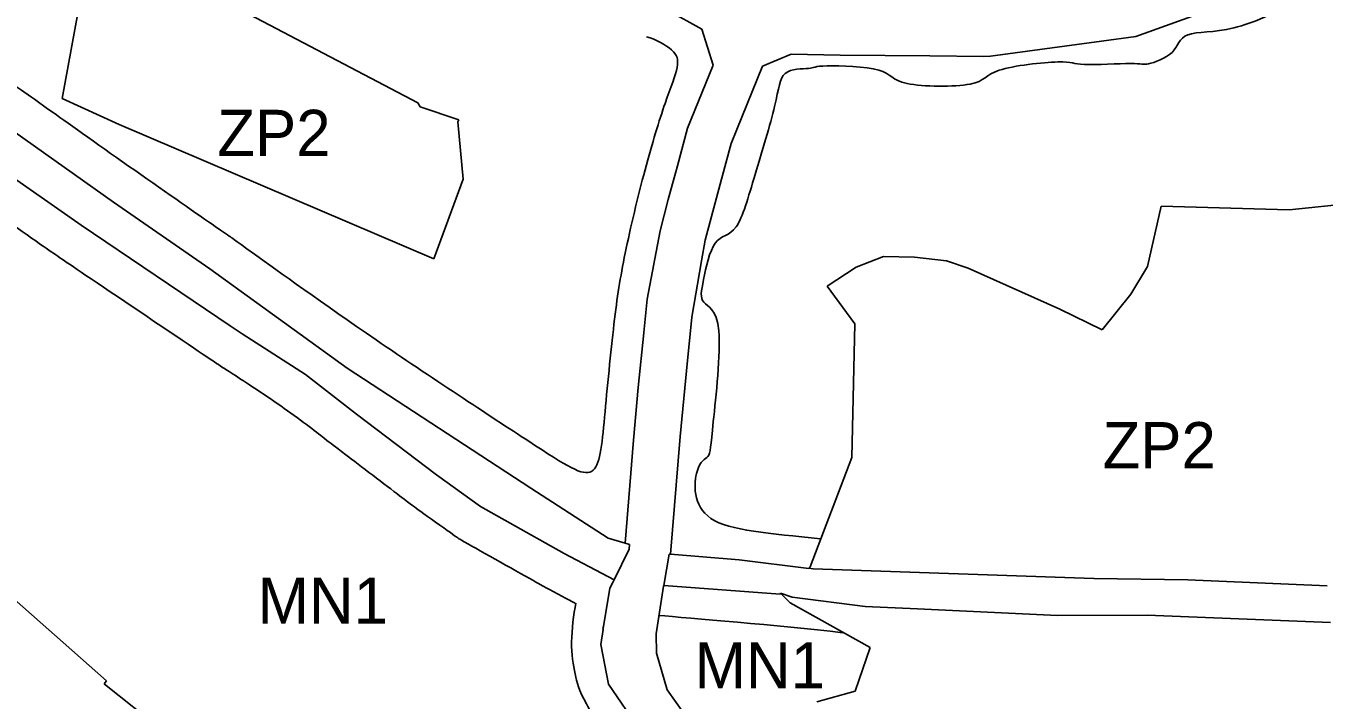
# Model space of a CAD drawing. Extents: x 7413438 to 7416393, y 5541665 to 5544118.
# Drawn here: x 7414274.3 to 7414442.9, y 5542859.3 to 5542946.8 of the extents above; entities that cross this region are included whole.
import ezdxf

# ---------------------------------------------------------------- set-up
doc = ezdxf.new("R2010")
doc.units = 0
for name, color, linetype in [('linie_rozgraniczajace', 7, 'Continuous'), ('linie_zabudowy_nieprzekraczalne', 7, 'Continuous'), ('oznaczenia_przeznaczen', 7, 'Continuous')]:
    doc.layers.add(name, color=color, linetype=linetype)

msp = doc.modelspace()

# ---------------------------------------------------------------- linework, layer by layer
at = {"layer": 'linie_rozgraniczajace'}
for p, q in [((7414283.71, 5542963.14), (7414278.97, 5542937.43)), ((7414325.17, 5542936.87), (7414296.63, 5542951.85)), ((7414357.68, 5542948.84), (7414362.05, 5542946.44)), ((7414418.45, 5542945.45), (7414428.42, 5542949.06)), ((7414362.05, 5542946.44), (7414363.54, 5542941.74)), ((7414413.98, 5542944.85), (7414418.45, 5542945.45)), ((7414399.57, 5542942.9), (7414413.98, 5542944.85)), ((7414369.96, 5542941.6), (7414373.68, 5542943.17)), ((7414373.68, 5542943.17), (7414380.04, 5542943.04)), ((7414380.04, 5542943.04), (7414391.66, 5542942.94)), ((7414391.66, 5542942.94), (7414398.64, 5542942.88)), ((7414398.64, 5542942.88), (7414399.57, 5542942.9)), ((7414363.54, 5542941.74), (7414360.21, 5542933.57)), ((7414366.62, 5542933.4), (7414369.96, 5542941.6)), ((7414278.97, 5542937.43), (7414286.37, 5542934.05)), ((7414325.47, 5542936.32), (7414325.17, 5542936.87)), ((7414330.48, 5542934.63), (7414325.47, 5542936.32)), ((7414286.37, 5542934.05), (7414327.24, 5542916.61)), ((7414330.39, 5542934.37), (7414330.48, 5542934.63)), ((7414331.06, 5542926.96), (7414330.39, 5542934.37)), ((7414360.21, 5542933.57), (7414358.89, 5542928.66)), ((7414272.83, 5542933.05), (7414285.64, 5542923.95)), ((7414365.88, 5542931.58), (7414366.62, 5542933.4)), ((7414281.45, 5542920.96), (7414266.51, 5542931.38)), ((7414364.63, 5542926.93), (7414365.88, 5542931.58)), ((7414358.89, 5542928.66), (7414357.71, 5542924.3)), ((7414327.24, 5542916.61), (7414331.06, 5542926.96)), ((7414362.51, 5542919.03), (7414364.63, 5542926.93)), ((7414285.64, 5542923.95), (7414298.14, 5542915.29)), ((7414357.71, 5542924.3), (7414356.63, 5542920.23)), ((7414419.97, 5542915.61), (7414421.72, 5542923.44)), ((7414421.72, 5542923.44), (7414438.34, 5542922.97)), ((7414438.34, 5542922.97), (7414446.71, 5542923.83)), ((7414300.81, 5542907.9), (7414281.45, 5542920.96)), ((7414356.63, 5542920.23), (7414354.98, 5542911.35)), ((7414362, 5542916.32), (7414362.51, 5542919.03)), ((7414382.1, 5542915.51), (7414385.67, 5542916.89)), ((7414385.67, 5542916.89), (7414389.7, 5542916.8)), ((7414389.7, 5542916.8), (7414393.86, 5542916.36)), ((7414298.14, 5542915.29), (7414316, 5542902.41)), ((7414360.77, 5542909.03), (7414362, 5542916.32)), ((7414378.35, 5542913.03), (7414382.1, 5542915.51)), ((7414393.86, 5542916.36), (7414396.67, 5542915.39)), ((7414396.67, 5542915.39), (7414408.56, 5542910.06)), ((7414417.78, 5542912), (7414419.97, 5542915.61)), ((7414380.86, 5542909.63), (7414378.35, 5542913.03)), ((7414414.06, 5542907.4), (7414417.78, 5542912)), ((7414354.98, 5542911.35), (7414354.54, 5542907.03)), ((7414408.56, 5542910.06), (7414414.06, 5542907.4)), ((7414360.05, 5542902.04), (7414360.77, 5542909.03)), ((7414381.94, 5542908.16), (7414380.86, 5542909.63)), ((7414302.34, 5542906.88), (7414300.81, 5542907.9)), ((7414310.6, 5542901.57), (7414302.34, 5542906.88)), ((7414354.54, 5542907.01), (7414353.8, 5542899.89)), ((7414354.54, 5542907.03), (7414354.54, 5542907.01)), ((7414381.54, 5542890.81), (7414381.94, 5542908.16)), ((7414317.19, 5542896.45), (7414310.6, 5542901.57)), ((7414316, 5542902.41), (7414339.85, 5542886.8)), ((7414359.26, 5542893.54), (7414360.05, 5542902.04)), ((7414353.8, 5542899.89), (7414353.2, 5542893.06)), ((7414327.59, 5542888.54), (7414317.19, 5542896.45)), ((7414353.2, 5542893.06), (7414352.09, 5542879.67)), ((7414358, 5542878.24), (7414359.26, 5542893.54)), ((7414376.15, 5542876.6), (7414381.54, 5542890.81)), ((7414333.31, 5542884.46), (7414327.59, 5542888.54)), ((7414339.85, 5542886.8), (7414349.9, 5542880.32)), ((7414339.25, 5542881.13), (7414333.31, 5542884.46)), ((7414344.17, 5542878.35), (7414339.25, 5542881.13)), ((7414349.9, 5542880.32), (7414352.09, 5542879.67)), ((7414352.09, 5542879.67), (7414352.68, 5542879.5)), ((7414284.74, 5542861.79), (7414266.01, 5542878.36)), ((7414350.68, 5542874.94), (7414344.17, 5542878.35)), ((7414352.63, 5542878.89), (7414350.68, 5542874.94)), ((7414352.68, 5542879.5), (7414352.63, 5542878.89)), ((7414357.11, 5542874.2), (7414357.81, 5542878.26)), ((7414357.81, 5542878.26), (7414358, 5542878.24)), ((7414358, 5542878.24), (7414366.93, 5542877.53)), ((7414366.93, 5542877.53), (7414375.94, 5542876.41)), ((7414375.94, 5542876.42), (7414376.15, 5542876.6)), ((7414375.94, 5542876.42), (7414376.51, 5542876.34)), ((7414375.94, 5542876.41), (7414375.94, 5542876.42)), ((7414376.51, 5542876.34), (7414412.99, 5542875.08)), ((7414350.55, 5542874.68), (7414350.13, 5542873.82)), ((7414350.68, 5542874.94), (7414350.55, 5542874.68)), ((7414412.99, 5542875.08), (7414413.02, 5542875.1)), ((7414413.02, 5542875.1), (7414425.17, 5542874.92)), ((7414425.17, 5542874.92), (7414443.27, 5542874.16)), ((7414350.13, 5542873.82), (7414349.27, 5542868.86)), ((7414357.09, 5542874.09), (7414356.13, 5542867.92)), ((7414357.11, 5542874.2), (7414357.09, 5542874.09)), ((7414372.22, 5542873.07), (7414357.11, 5542874.2)), ((7414372.26, 5542873.2), (7414372.22, 5542873.07)), ((7414372.27, 5542873.2), (7414372.26, 5542873.2)), ((7414373.53, 5542871.94), (7414372.27, 5542873.2)), ((7414373.79, 5542872.68), (7414372.27, 5542873.2)), ((7414383.91, 5542866.12), (7414373.53, 5542871.94)), ((7414383.28, 5542871.46), (7414373.79, 5542872.68)), ((7414390.07, 5542871.17), (7414383.28, 5542871.46)), ((7414408.24, 5542870.27), (7414390.07, 5542871.17)), ((7414408.26, 5542870.29), (7414408.24, 5542870.27)), ((7414419.89, 5542870.31), (7414408.26, 5542870.29)), ((7414443.73, 5542869.37), (7414419.89, 5542870.31)), ((7414349.25, 5542868.49), (7414348.96, 5542866.51)), ((7414349.27, 5542868.86), (7414349.22, 5542868.58)), ((7414349.22, 5542868.58), (7414349.25, 5542868.49)), ((7414356.13, 5542867.92), (7414356.16, 5542865.4)), ((7414348.96, 5542866.51), (7414349.96, 5542861.38)), ((7414381.99, 5542860.47), (7414383.91, 5542866.12)), ((7414356.16, 5542865.4), (7414357.54, 5542860.63)), ((7414284.43, 5542861.41), (7414284.74, 5542861.79)), ((7414284.48, 5542861.39), (7414284.43, 5542861.41)), ((7414334.49, 5542821.6), (7414284.48, 5542861.39)), ((7414349.96, 5542861.38), (7414355.97, 5542852.55)), ((7414357.54, 5542860.63), (7414361.08, 5542855.72)), ((7414377, 5542859.07), (7414381.99, 5542860.47))]:
    msp.add_line(p, q, dxfattribs=at)
at = {"layer": 'linie_zabudowy_nieprzekraczalne'}
for points in [[(7414508.57, 5543008.49), (7414498.05, 5543011.01), (7414482.82, 5543014.57), (7414466.45, 5543018.77), (7414466.58, 5543021.39), (7414454.91, 5543021.58), (7414446.03, 5543023.6), (7414439.09, 5543025.32), (7414436.2, 5543024.38), (7414434.02, 5543022.75), (7414433.67, 5543013.7), (7414434.74, 5543013.63), (7414436.82, 5543009.35), (7414439.42, 5543005.48), (7414441.42, 5543001.64), (7414441.84, 5542997.01), (7414443.29, 5542997.15), (7414446.06, 5542983.5), (7414446.66, 5542972.27), (7414444.62, 5542972.19), (7414444.71, 5542964.02), (7414443.51, 5542956.57), (7414441.21, 5542952.53), (7414439.68, 5542950.09), (7414430.8, 5542945.76), (7414424.13, 5542946.32), (7414423.85, 5542943.15), (7414419.34, 5542941.55), (7414419.25, 5542942.16), (7414410.29, 5542941.57), (7414410.19, 5542942.53), (7414398.73, 5542941.28), (7414399.01, 5542938.87), (7414386.65, 5542938.96), (7414386.72, 5542941.47), (7414376.67, 5542941.82), (7414376.65, 5542941.2), (7414372.17, 5542941.36), (7414372.04, 5542937.46), (7414368.78, 5542927.14), (7414366.7, 5542919.38), (7414363.5, 5542919.82), (7414362.16, 5542913.25), (7414361.63, 5542910.64), (7414365.18, 5542909.93), (7414363.25, 5542893.09), (7414363.14, 5542890.51), (7414361.23, 5542890.49), (7414360.59, 5542881.54), (7414370.8, 5542880.96), (7414377.49, 5542880.26)], [(7414240.16, 5542991.91), (7414241.96, 5542989.98), (7414242.1, 5542989.82), (7414246.63, 5542984.53), (7414246.67, 5542984.48), (7414246.87, 5542984.22), (7414247.05, 5542983.95), (7414247.22, 5542983.67), (7414247.37, 5542983.38), (7414247.5, 5542983.08), (7414247.55, 5542982.93), (7414248.56, 5542980.04), (7414250.04, 5542976.08), (7414250.09, 5542975.92), (7414254.4, 5542963.03), (7414259.61, 5542949.68), (7414263.34, 5542945.99), (7414265.03, 5542944.76), (7414265.22, 5542944.61), (7414265.47, 5542944.4), (7414265.7, 5542944.17), (7414265.75, 5542944.11), (7414275.66, 5542937.11), (7414275.67, 5542937.1), (7414288.45, 5542928.02), (7414300.93, 5542919.38), (7414300.97, 5542919.36), (7414301.01, 5542919.33), (7414318.78, 5542906.52), (7414342.51, 5542890.98), (7414348.64, 5542887.02), (7414349.3, 5542894.98), (7414350.7, 5542909.29), (7414351.82, 5542916.53), (7414354.71, 5542928.72), (7414357.45, 5542937.52), (7414359.24, 5542941.89), (7414358.67, 5542943.69), (7414356.12, 5542945.09), (7414354.88, 5542945.44)], [(7414345.63, 5542871.9), (7414341.8, 5542873.9), (7414341.8, 5542873.9), (7414341.66, 5542873.98), (7414336.75, 5542876.75), (7414330.81, 5542880.08), (7414330.65, 5542880.17), (7414330.38, 5542880.35), (7414330.35, 5542880.37), (7414324.63, 5542884.45), (7414324.51, 5542884.54), (7414314.11, 5542892.45), (7414314.07, 5542892.48), (7414307.65, 5542897.47), (7414299.58, 5542902.65), (7414299.49, 5542902.71), (7414278.6, 5542916.79), (7414278.53, 5542916.84), (7414263.6, 5542927.26), (7414263.58, 5542927.28), (7414263.56, 5542927.29), (7414257.17, 5542931.84), (7414257.03, 5542930.07), (7414257.02, 5542929.27), (7414257.02, 5542928.48), (7414257.02, 5542927.68), (7414257.01, 5542926.88), (7414257.01, 5542926.08), (7414257, 5542925.28), (7414257, 5542924.49), (7414256.99, 5542923.69), (7414256.99, 5542922.91), (7414256.98, 5542922.12), (7414256.98, 5542921.35), (7414256.98, 5542920.58), (7414256.97, 5542919.83), (7414256.97, 5542919.08), (7414256.96, 5542918.35), (7414256.96, 5542917.63), (7414256.95, 5542916.93), (7414256.95, 5542916.24), (7414256.95, 5542915.57), (7414256.94, 5542914.92), (7414256.94, 5542914.29), (7414256.94, 5542913.68), (7414256.93, 5542913.09), (7414256.93, 5542912.52), (7414256.93, 5542911.96), (7414256.93, 5542911.41), (7414256.93, 5542910.88), (7414256.93, 5542910.35), (7414256.92, 5542909.82), (7414256.92, 5542909.31), (7414256.92, 5542908.79), (7414256.92, 5542908.27), (7414256.92, 5542907.75), (7414256.92, 5542907.22), (7414256.92, 5542906.69), (7414256.92, 5542906.15), (7414256.92, 5542905.6), (7414256.92, 5542905.03), (7414256.92, 5542904.45), (7414256.92, 5542903.85), (7414256.92, 5542903.23), (7414256.92, 5542902.59), (7414256.92, 5542901.93), (7414256.93, 5542901.24), (7414256.93, 5542900.54), (7414256.93, 5542899.83), (7414256.93, 5542899.1), (7414256.93, 5542898.36), (7414256.92, 5542897.61), (7414256.92, 5542896.86), (7414256.92, 5542896.1), (7414256.92, 5542895.35), (7414256.91, 5542894.59), (7414256.9, 5542893.83), (7414256.9, 5542893.08), (7414256.89, 5542892.34), (7414256.88, 5542891.61), (7414256.86, 5542890.89), (7414256.85, 5542890.19), (7414256.83, 5542889.5), (7414256.81, 5542888.83), (7414256.79, 5542888.18), (7414256.77, 5542887.55), (7414256.74, 5542886.94), (7414256.69, 5542886.33), (7414256.63, 5542885.7), (7414256.54, 5542885.05), (7414256.42, 5542884.35), (7414256.26, 5542883.6), (7414256.05, 5542882.78), (7414255.8, 5542881.88), (7414255.49, 5542880.88), (7414255.11, 5542879.77), (7414254.66, 5542878.53), (7414254.14, 5542877.16), (7414253.54, 5542875.64), (7414252.85, 5542873.95), (7414252.06, 5542872.08), (7414251.17, 5542870.02), (7414250.18, 5542867.75), (7414249.07, 5542865.25), (7414246.49, 5542859.56)], [(7414320.5, 5542797.87), (7414331.67, 5542823.78), (7414335.39, 5542824.67), (7414336.62, 5542826.65), (7414340.94, 5542833.52), (7414345.97, 5542839.2), (7414350.03, 5542843.52), (7414351.66, 5542851.67), (7414346.28, 5542859.68), (7414345.6, 5542862.52), (7414344.9, 5542866.58), (7414345.43, 5542870.43), (7414345.69, 5542871.88)], [(7414380.37, 5542868.05), (7414371.9, 5542869.06), (7414360.37, 5542869.94), (7414356.45, 5542870.3)]]:
    msp.add_open_spline(points, degree=3, dxfattribs=at)

# ---------------------------------------------------------------- texts
at = {"layer": 'oznaczenia_przeznaczen'}
for s, p in [('ZP2', (7414299.13, 5542929.95)), ('ZP2', (7414414.11, 5542889.4)), ('MN1', (7414304.35, 5542869.22)), ('MN1', (7414361.11, 5542860.81))]:
    msp.add_text(s, height=6, dxfattribs=at).set_placement(p)

doc.saveas('drawing.dxf')
